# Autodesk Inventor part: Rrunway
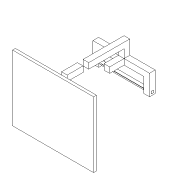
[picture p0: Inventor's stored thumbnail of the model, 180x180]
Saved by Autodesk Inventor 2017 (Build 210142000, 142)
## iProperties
Created: 2015-03
Part Number: Rrunway
Document SubType Name: Modeling
Designer: Administrator
Density: 1 g/cm^3
Mass: 3.06654 g
Surface Area: 21.2082 cm^2
Volume: 3.06654 cm^3
Material: Generic
Appearance: Snow
Author: Administrator
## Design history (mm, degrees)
sketch "Sketch1"
  geometry: L1 (0, 0)-(0, 3); L2 (0, 3)-(-40, 3); L3 (-40, 3)-(-40, 7.5); L4 (-40, 7.5)-(-50, 7.5); L5 (-50, 7.5)-(-50, 0); L6 (-50, 0)-(0, 0); L7 (0, 3)-(40, 3); L8 (40, 3)-(40, 7.5); L9 (40, 7.5)-(50, 7.5); L10 (50, 7.5)-(50, 0); L11 (50, 0)-(0, 0)
  constraints: 22 end point, 4 parallel, 4 symmetric about line, 1 perpendicular, 1 vertical, 1 other
  dimensions: "d0" = 3 distance of L1.start L1.end; "d1" = 7.5 distance between parallel lines of L4 L6; "d2" = 10 distance of L3.end L4.end; "d3" = 40 distance of L1.end L2.end
revolve "Revolution1" sketch "Sketch1" stored, may be unused: angle "d4" = 90 deg
sketch "Sketch2"
  geometry: L1 (5, 5)-(5, -5); L2 (5, -5)-(-5, -5); L3 (-5, -5)-(-5, 5); L4 (-5, 5)-(5, 5); C1 r 13.184 at (0, 0); 1 further point
  constraints: 8 end point, 1 centre point, 1 coincident, 10 other
  dimensions: "d5" = 10 distance of L3.end L1.start
extrude "Extrusion1" cut sketch "Sketch2" stored distance "d6" = 10; taper "d7" = 0 deg
sketch "Sketch5"
  geometry: C1 r 3 at (5, 4.899) reference; C2 r 2.5 at (5, 4.899); 1 further point
  constraints: 1 centre point
  dimensions: "d12" = 5 diameter of C2
extrude "Extrusion2" join sketch "Sketch5" distance "d13" = 0.1; taper "d14" = 0 deg
mirror "Mirror1"
sketch "Sketch6"
  geometry: L1 (40, 3)-(-40, 3) reference; L2 (40, -3)-(-40, -3) reference; L3 (40, 3)-(40, -3) reference; L4 (-40, 3)-(-40, -3) reference; L5 (40, 0)-(-40, 0); L6 (37, 1)-(-37, 1); L7 (37, -1)-(-37, -1); A1 r 1 centre (37, 0) between (37, -1) and (37, 1); A2 r 1 centre (-37, 0) between (-37, 1) and (-37, -1); 1 further point
  constraints: 6 end point, 4 point on circle, 2 centre point, 2 midpoint, 2 point on line, 2 tangent, 1 equal radius
  dimensions: "d15" = 2 diameter of A2; "d16" = 3 distance from line of A2.centre L4; "d17" = 3 distance from line of A1.centre L3
extrude "Extrusion3" join sketch "Sketch6" distance "d18" = 3.5; taper "d19" = 0 deg
sketch "Sketch4"
  geometry: L1 (0, -0.101)-(0, 9.899) reference; L2 (10, 9.899)-(10, -0.101) reference; L3 (90, -0.101)-(90, 9.899) reference; L4 (100, 9.899)-(100, -0.101) reference; L5 (10, 4.899)-(90, 4.899); L6 (50, 4.899)-(50, -9.101); L7 (50, -9.101)-(18, -9.101); L8 (18, -9.101)-(18, -53.101); L9 (18, -53.101)-(82, -53.101); L10 (82, -53.101)-(82, -9.101); L11 (82, -9.101)-(50, -9.101); L12 (100, -0.101)-(90, -0.101) reference; L13 (100, 9.899)-(90, 9.899) reference; L14 (10, -0.101)-(0, -0.101) reference; L15 (10, 9.899)-(0, 9.899) reference
  constraints: 14 end point, 5 perpendicular, 2 midpoint, 1 point on line, 1 vertical
  dimensions: "d8" = 64 distance of L8.end L9.end; "d9" = 32 distance between parallel lines of L8 L6; "d10" = 44 distance of L9.end L10.end; "d11" = 14 distance of L6.start L6.end
  node "Projected Loop3"
  node "Projected Loop4"
sketch "Sketch7"
  geometry: L1 (0, 0)-(0, 10) reference; L2 (10, 0)-(0, 0) reference; L3 (10, 10)-(10, 0) reference; L4 (10, 10)-(0, 10) reference; L5 (90, 0)-(90, 10) reference; L6 (100, 0)-(90, 0) reference; L7 (100, 10)-(100, 0) reference; L8 (100, 10)-(90, 10) reference; L9 (0, 0)-(0, 10) reference; L10 (100, 10)-(100, 0) reference; L11 (100, 10)-(100, 50); L12 (100, 50)-(0, 50); L13 (0, 50)-(0, 10); L14 (10, 10)-(10, 40); L15 (10, 40)-(90, 40); L16 (90, 40)-(90, 10); L17 (0, 10)-(10, 10); L18 (90, 10)-(100, 10); L19 (10, 0)-(10, -16); L20 (100, 0)-(90, 0) reference; L21 (90, 0)-(90, -16); L22 (10, -16)-(90, -16); L23 (100, 0)-(100, -26); L24 (100, -26)-(0, -26); L25 (0, -26)-(0, 0); L26 (10, 0)-(0, 0); L27 (10, 0)-(0, 0) reference; L28 (90, 0)-(100, 0); 1 further point
  constraints: 32 end point, 5 perpendicular, 4 parallel, 3 horizontal, 2 vertical, 1 collinear, 2 other
  dimensions: "d22" = 10 distance between parallel lines of L13 L14 (derived); "d23" = 10 distance between parallel lines of L16 L11; "d25" = 10 distance between parallel lines of L12 L15; "d28" = 16 distance of L2.start L19.end; "d29" = 10 distance between parallel lines of L23 L21
extrude "Extrusion4" join sketch "Sketch7" stored distance "d26" = 3.5; taper "d27" = 0 deg
sketch "Sketch8"
  geometry: L1 (0, 0)-(0, 36) reference; L2 (10, 0)-(0, 0) reference; L3 (10, 26)-(10, 0) reference; L4 (90, 26)-(10, 26) reference; L5 (90, 0)-(90, 26) reference; L6 (100, 0)-(90, 0) reference; L7 (100, 36)-(100, 0) reference; L8 (0, 36)-(100, 36) reference; L9 (0, 36)-(100, 36) reference; L10 (50, 36)-(50, 26); L11 (45, 26)-(55, 26); L12 (55, 26)-(55, 36); L13 (55, 36)-(45, 36); L14 (45, 36)-(45, 26); 1 further point
  constraints: 10 end point, 2 midpoint, 2 parallel, 2 point on line, 1 horizontal, 1 perpendicular
  dimensions: "d30" = 10 distance between parallel lines of L12 L14; "d31" = 5 distance between parallel lines of L12 L10
extrude "Extrusion5" join sketch "Sketch8" distance "d32" = 25.5; taper "d33" = 0 deg
sketch "Sketch9"
  geometry: L1 (-5, 31)-(-5, 21) reference; L2 (-5, 31)-(-30.5, 31) reference; L3 (-30.5, 21)-(-30.5, 31) reference; L4 (-5, 21)-(-30.5, 21) reference; L5 (5, -5)-(5, 31) reference; L6 (5, 31)-(-5, 31) reference; L7 (-5, 31)-(-5, -5) reference; L8 (-5, -5)-(5, -5) reference; L9 (-5, 31)-(-5, 46); L10 (5, 56)-(-67.5, 56); L11 (-67.5, 56)-(-67.5, 46); L12 (-67.5, 46)-(-5, 46); L13 (5, 31)-(-5, 31) reference; L14 (5, 56)-(5, 31); L15 (5, 31)-(-5, 31); L16 (-67.5, 46)-(-77.5, 46); L17 (-77.5, 46)-(-77.5, 56); L18 (-77.5, 56)-(-67.5, 56); L19 (-67.5, 56)-(-67.5, 46); L20 (-77.5, 46)-(-105.5, 46); L21 (-105.5, 46)-(-105.5, 56); L22 (-105.5, 56)-(-77.5, 56); L23 (-77.5, 56)-(-77.5, 46); L24 (-105.5, 56)-(-115.5, 56); L25 (-115.5, 56)-(-115.5, 46); L26 (-115.5, 46)-(-105.5, 46); L27 (-105.5, 46)-(-105.5, 56); L28 (-115.5, 46)-(-120.5, 46); L29 (-120.5, 46)-(-120.5, 56); L30 (-120.5, 56)-(-115.5, 56); L31 (-115.5, 56)-(-115.5, 46); C1 r 2.5 at (0, 0) reference; 1 further point
  constraints: 44 end point, 9 perpendicular, 8 parallel, 4 horizontal, 1 vertical
  dimensions: "d34" = 10 distance between parallel lines of L9 L14 (derived); "d35" = 10 distance between parallel lines of L10 L12; "d39" = 62.5 distance between parallel lines of L11 L9; "d40" = 15 distance between parallel lines of L12 L6; "d41" = 10 distance between parallel lines of L16 L18; "d42" = 10 distance of L17.end L18.end; "d43" = 28 distance of L21.end L22.end; "d44" = 10 distance of L24.end L25.end; "d45" = 10 distance of L28.end L29.end; "d46" = 5 distance of L29.end L30.end; "d47" = 10 distance of L21.end L24.end
extrude "Extrusion6" join sketch "Sketch9" stored distance "d37" = 10; taper "d38" = 0 deg
sketch "Sketch10"
  geometry: L1 (10, 0)-(0, 0) reference; L2 (10, 10)-(10, 0) reference; L3 (10, 10)-(0, 10) reference; L4 (0, 0)-(0, 10) reference; L5 (5, -46)-(5, 10); L6 (5, -46)-(5, -96); L7 (5, -96)-(-66.609, -96); L8 (-66.609, -96)-(-66.609, 20); L9 (-66.609, 20)-(5, 20); L10 (5, 20)-(5, 8.864); L11 (5, -96)-(76.609, -96); L12 (76.609, -96)-(76.609, 20); L13 (76.609, 20)-(5, 20); L14 (-66.609, -96)-(76.609, -96); L15 (76.609, -96)-(76.609, 20); L16 (76.609, 20)-(-66.609, 20); L17 (-66.609, 20)-(-66.609, -96)
  constraints: 26 end point, 4 perpendicular, 3 point on line, 2 parallel, 2 symmetric about line, 1 horizontal, 1 midpoint
  dimensions: "d48" = 10 distance between parallel lines of L13 L3; "d49" = 50 distance of L5.start L6.end
extrude "Extrusion7" join sketch "Sketch10" distance "d50" = 5; taper "d51" = 0 deg
body "Solid1"
node "Projected Loop5"
node "Projected Loop6"
node "Projected Loop7"
node "Projected Loop8"
node "Projected Loop9"
node "Projected Loop10"
node "Projected Loop11"
